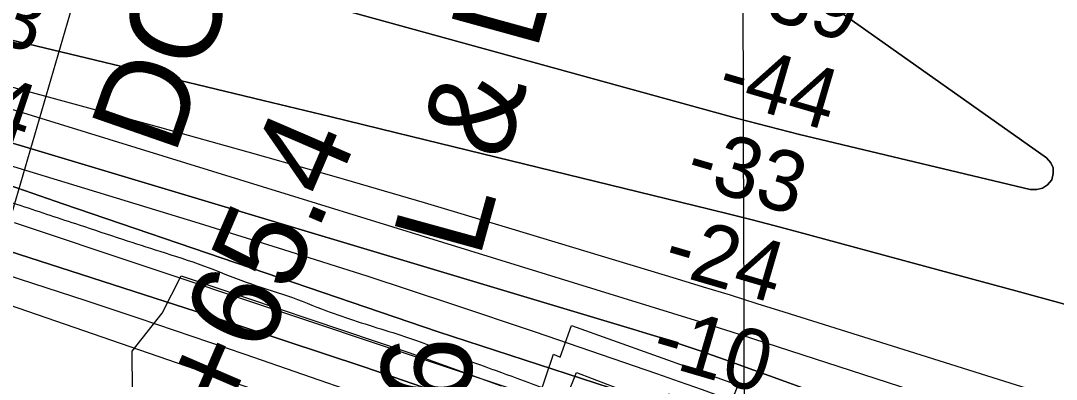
# Model space of a CAD drawing. Extents: x 3361039 to 3398939, y 576572 to 602007.
# Drawn here: x 3390699 to 3391844, y 584956 to 585353 of the extents above; entities that cross this region are included whole.
import ezdxf

# ---------------------------------------------------------------- set-up
doc = ezdxf.new("R2010")
doc.units = 0
for name, color, linetype in [('V-BLDG-OTLN', 7, 'Continuous'), ('V-CHAN-DOCK', 7, 'Continuous'), ('V-CHAN-NAID', 7, 'Continuous'), ('V-GRID-MAJR', 7, 'Continuous'), ('V-RIVR-EDGE', 7, 'Continuous'), ('V-RIVR-RANG', 7, 'Continuous'), ('V-RRAP-RVMT', 7, 'Continuous'), ('V-SITE-VEGE', 7, 'Continuous'), ('V-SURV-IDEN', 7, 'Continuous'), ('V-TOPO-DPTH', 7, 'Continuous'), ('V-TOPO-GNAM-IDEN', 7, 'Continuous'), ('V-TOPO-MINR', 7, 'Continuous'), ('V-TOPO-WATR', 7, 'Continuous')]:
    doc.layers.add(name, color=color, linetype=linetype)

msp = doc.modelspace()

# ---------------------------------------------------------------- linework, layer by layer
at = {"layer": 'V-BLDG-OTLN'}
msp.add_lwpolyline([(3391313.5, 584963.8), (3391365.3, 584943.8), (3391354.9, 584916.8), (3391302.7, 584937)], close=True, dxfattribs=at)
at = {"layer": 'V-CHAN-DOCK'}
msp.add_lwpolyline([(3391216.1, 584431.7), (3391319.4, 584920.6), (3391309.9, 584925.2), (3391300.8, 584899.4), (3391295.2, 584901.5), (3391304, 584926.4), (3391272, 584937.1), (3391287.9, 584984), (3391295.1, 584980.8), (3391307.7, 585015.7), (3391489.2, 584950.8), (3391490.8, 584946.8), (3391478.1, 584915.9), (3391415.4, 584939.9), (3391397.3, 584891.4), (3391323, 584915.4), (3391227.7, 584465.3), (3391220.5, 584430.8), (3391216.1, 584431.7)], dxfattribs=at)
at = {"layer": 'V-GRID-MAJR'}
msp.add_spline([(3391508.2, 582029.8), (3391489.7, 588089), (3391471.2, 594150.1), (3391452.7, 600211.2), (3391452.7, 600213.1)], degree=3, dxfattribs=at)
at = {"layer": 'V-RIVR-EDGE'}
msp.add_spline([(3387368.6, 585771), (3387389, 585767.6), (3387407.3, 585766.1), (3387418.2, 585761.7), (3387425.5, 585756.5), (3387441.6, 585752.8), (3387452.6, 585751.4), (3387462.1, 585753.9), (3387477.4, 585758.2), (3387482.9, 585759.3), (3387491.7, 585759.3), (3387502.3, 585758.2), (3387510.3, 585756.3), (3387521.6, 585753), (3387530.1, 585752.3), (3387538.5, 585752.2), (3387549.8, 585752.2), (3387558.9, 585755.5), (3387571.4, 585756.9), (3387583.4, 585757.3), (3387598.4, 585756.1), (3387629.8, 585749.5), (3387659.8, 585743.5), (3387703.3, 585736.8), (3387727.4, 585734.2), (3387739.1, 585733.5), (3387750.8, 585734.2), (3387753.7, 585731.6), (3387763.2, 585723.9), (3387774.5, 585720.6), (3387790.6, 585719.8), (3387800.1, 585721.6), (3387814, 585720.1), (3387824.6, 585720.1), (3387847.3, 585714.2), (3387884.2, 585709.4), (3387930.2, 585702.7), (3387980.6, 585701.1), (3388035.1, 585696.5), (3388076, 585694.6), (3388096.9, 585693.8), (3388120.3, 585690.5), (3388145.1, 585685.3), (3388171.8, 585682.3), (3388198.8, 585676.8), (3388222.6, 585669.4), (3388245.6, 585660.6), (3388260.9, 585655.4), (3388279.6, 585655.4), (3388291.3, 585658.3), (3388298.9, 585663.7), (3388299.3, 585666.3), (3388299, 585670.7), (3388290.6, 585674.4), (3388291.7, 585677.3), (3388293.9, 585678.4), (3388303, 585677.6), (3388318.7, 585676.5), (3388334.1, 585672.8), (3388354.1, 585663.6), (3388357.1, 585659.9), (3388363.3, 585658.1), (3388368.4, 585658.1), (3388371, 585661), (3388375.3, 585662.1), (3388379, 585661.3), (3388383, 585659.1), (3388383.7, 585654.4), (3388384.1, 585649.3), (3388389.9, 585647.4), (3388406, 585642.3), (3388468.9, 585637.7), (3388491.5, 585635.8), (3388534.6, 585628.4), (3388578.1, 585619.2), (3388610.6, 585613.6), (3388635.9, 585612.1), (3388727.9, 585599.4), (3388768.5, 585591.7), (3388822.6, 585580.9), (3388865, 585570.6), (3388906.6, 585562.8), (3388924.1, 585559.5), (3388938.8, 585562), (3388961.4, 585563.4), (3388974.2, 585560.1), (3389007.5, 585553.4), (3389018.8, 585554.5), (3389027.2, 585555.9), (3389037.1, 585555.9), (3389051.7, 585553.7), (3389061.2, 585553.3), (3389081.3, 585552.1), (3389098.1, 585551), (3389120.4, 585548.7), (3389143.4, 585546.5), (3389160.2, 585542.1), (3389200.8, 585534.7), (3389222.3, 585525.1), (3389247.2, 585519.2), (3389280.4, 585509.6), (3389307.5, 585497.8), (3389334.5, 585487.2), (3389349.5, 585483.1), (3389361.5, 585483.1), (3389382.7, 585479), (3389397, 585476.8), (3389416.7, 585468.7), (3389441.9, 585458.4), (3389464.9, 585451.4), (3389479.5, 585449.2), (3389506.2, 585446.2), (3389533.2, 585447.2), (3389558.5, 585444.2), (3389577.8, 585437.9), (3389603.4, 585431.3), (3389618.7, 585425.1), (3389639.2, 585415.1), (3389657.8, 585410.3), (3389693.2, 585404.8), (3389768.9, 585383), (3389806.5, 585373), (3389854.3, 585362.3), (3389881.7, 585358.6), (3389913.9, 585354.5), (3389953.7, 585349.3), (3390008.2, 585341.8), (3390037.8, 585336.3), (3390074.3, 585327.8), (3390128, 585312.7), (3390164.5, 585301.6), (3390200.7, 585289.8), (3390292.7, 585255.6), (3390327.1, 585241.3), (3390360.7, 585231.7), (3390404.5, 585221), (3390454.9, 585214.3), (3390483.1, 585210.5), (3390491.8, 585209.4), (3390494.4, 585207.2), (3390501.3, 585201), (3390507.9, 585200.6), (3390527.3, 585196.2), (3390545.9, 585195), (3390557.6, 585194.3), (3390574.4, 585189.8), (3390605.5, 585179.5), (3390698.6, 585148.2), (3390763.2, 585126.9), (3390811.1, 585111), (3390852.4, 585097.8), (3390900.9, 585081.6), (3390948.1, 585063.5), (3390993.7, 585048.4), (3391036.8, 585031.9), (3391070.8, 585020.1), (3391140.5, 584997.6), (3391201.5, 584974.1), (3391247.5, 584957.5), (3391310.7, 584933.6), (3391362.2, 584914.8), (3391400.6, 584900.1), (3391441.8, 584885.7), (3391505.4, 584861.1), (3391563.5, 584841.9), (3391658.8, 584807.3), (3391712.8, 584786), (3391758.8, 584767.3), (3391796.1, 584749.6), (3391880.4, 584718.3), (3391926.8, 584701.4), (3391969.2, 584685.2), (3392003.9, 584666.9), (3392040, 584650.3), (3392077.6, 584636), (3392135.7, 584613.2), (3392164.9, 584598.1), (3392196, 584583.8), (3392224.8, 584578.2), (3392263.5, 584567.9), (3392290.6, 584559.8), (3392322.7, 584546.5), (3392396.5, 584512.7), (3392439.9, 584496.2), (3392471.7, 584484.8), (3392502, 584473.3), (3392510.8, 584467.5), (3392535.2, 584458.3), (3392606.1, 584432.9), (3392632.4, 584421.5), (3392666.7, 584406.8), (3392715.6, 584386.9), (3392777.4, 584364.8), (3392827, 584348.3), (3392863.6, 584335.4), (3392897.9, 584321.8), (3392928.6, 584307.8), (3392965.4, 584294.9), (3393010, 584279.1), (3393054.6, 584263.2), (3393092.5, 584248.5), (3393195.2, 584206.6), (3393234.2, 584187.9), (3393264.5, 584173.5), (3393294.1, 584162.1), (3393336.8, 584147.4), (3393374.5, 584136.3), (3393402.2, 584127.5), (3393414.3, 584119.8), (3393435.4, 584109.1), (3393459.2, 584098.1), (3393478.9, 584087.5), (3393513.6, 584076.4), (3393541.7, 584067.2), (3393588.1, 584047.4), (3393643.2, 584028.9), (3393668.4, 584018.3), (3393699.8, 584005), (3393737.1, 583991.8), (3393781.7, 583976), (3393884.7, 583943.2), (3393927, 583928.8), (3393981.1, 583908.2), (3394043.9, 583885.4), (3394095.8, 583868.1), (3394154.9, 583847.1), (3394200.2, 583830.5), (3394247, 583816.2), (3394293, 583801.4), (3394349.6, 583781.2), (3394409.1, 583754.7), (3394451.8, 583730.5), (3394470.5, 583720.2), (3394481.8, 583715.4), (3394494.2, 583713.6), (3394502.6, 583708.1), (3394507.3, 583700.4), (3394511.3, 583697.8), (3394522.7, 583692.3), (3394557.3, 583675.8), (3394600.4, 583659.9), (3394658.1, 583638.9), (3394704.5, 583623.5), (3394760.4, 583607.6), (3394824, 583588.8), (3394867.8, 583570.8), (3394925.9, 583546.9), (3394972.2, 583528.9), (3394995.6, 583520), (3395064.7, 583504.2), (3395088.4, 583499.3), (3395120.2, 583491.6), (3395149.1, 583480.5), (3395173.2, 583476.8), (3395201.3, 583471.3), (3395236.4, 583459.9), (3395256.8, 583451.8), (3395280.9, 583445.5), (3395300.3, 583445.1), (3395316.7, 583440.7), (3395324.4, 583433.3), (3395335.3, 583426), (3395353.6, 583417.9), (3395398.9, 583403.9), (3395426.3, 583397.2), (3395442, 583391), (3395455.9, 583383.3), (3395476, 583377.8), (3395495.7, 583369.3), (3395511, 583368.2), (3395530.4, 583365.9), (3395550.5, 583361.8), (3395654.6, 583334.9), (3395704.7, 583322.4), (3395743.7, 583306.9), (3395765.3, 583295.5), (3395788.3, 583286.3), (3395816.4, 583278.9), (3395861.7, 583270.8), (3395916.2, 583261.5), (3395960.7, 583252.6), (3396008.6, 583242.6), (3396060.8, 583230.5), (3396093.4, 583222.3), (3396135.4, 583208.7), (3396170.1, 583199.8), (3396204.4, 583191.3), (3396254.8, 583177.3), (3396301.2, 583165.9), (3396364.4, 583152.9), (3396399.1, 583144.4), (3396426.9, 583138.5), (3396463.1, 583133), (3396489.8, 583132.9), (3396523.4, 583130.2), (3396607.8, 583114), (3396670.3, 583102.1), (3396708.3, 583095.4), (3396743, 583089.5), (3396775.1, 583083.9)], degree=3, dxfattribs=at)
at = {"layer": 'V-RRAP-RVMT'}
msp.add_lwpolyline([(3390685.7, 585129), (3390783.7, 585465.6), (3390648.8, 585504.8), (3390652.2, 585515.7), (3390497.3, 585563.3), (3390495.9, 585558.8), (3390372.4, 585595.5), (3390373.7, 585599.7), (3390218.6, 585646.7), (3390217.1, 585641.8), (3390080.1, 585682.4), (3390078.7, 585677.7), (3389945.1, 585716.3), (3389952.9, 585741.6), (3389804, 585787.6), (3389799.7, 585774.2), (3389655.5, 585815.8), (3389654.5, 585812.6)], dxfattribs=at)
at = {"layer": 'V-SITE-VEGE'}
msp.add_lwpolyline([(3390822.2, 584942.7), (3390821.7, 584987.3), (3390855, 585029.4), (3390875.9, 585070.5), (3391128, 584985.7), (3391230.1, 584948.8)], dxfattribs=at)
at = {"layer": 'V-TOPO-DPTH'}
for points in [[(3391605.6, 585361.8), (3391833.3, 585200.8), (3391837.9, 585195.5), (3391840.7, 585189.8), (3391840.7, 585183.5), (3391839, 585176.7), (3391834.3, 585171.2), (3391829, 585167.3), (3391822.5, 585165.8), (3391815.2, 585166), (3391583.2, 585221.1), (3391560.2, 585226.7), (3391537.2, 585232.5), (3391514.3, 585238.5), (3391491.5, 585244.6), (3390782.9, 585439.8)], [(3390782.9, 585439.8), (3391491.5, 585244.6), (3391514.3, 585238.5), (3391537.2, 585232.5), (3391560.2, 585226.7), (3391583.2, 585221.1), (3391815.2, 585166), (3391822.5, 585165.8), (3391829, 585167.3), (3391834.3, 585171.2), (3391839, 585176.7), (3391840.7, 585183.5), (3391840.7, 585189.8), (3391837.9, 585195.5), (3391833.3, 585200.8), (3391605.6, 585361.8)], [(3391896.5, 585027.4), (3391799.4, 585053.9), (3391702.2, 585080.3), (3391555.3, 585120), (3391531.6, 585126.3), (3391507.8, 585132.5), (3391483.9, 585138.5), (3391460.1, 585144.4), (3391114.1, 585228.6), (3391040.5, 585246.5), (3390966.9, 585264.3), (3390893.3, 585282.1), (3390819.7, 585299.8), (3390742.8, 585318.2), (3390707.6, 585326.6), (3390672.4, 585334.9)], [(3390672.4, 585334.9), (3390707.6, 585326.6), (3390742.8, 585318.2), (3390819.7, 585299.8), (3390893.3, 585282.1), (3390966.9, 585264.3), (3391040.5, 585246.5), (3391114.1, 585228.6), (3391460.1, 585144.4), (3391483.9, 585138.5), (3391507.8, 585132.5), (3391531.6, 585126.3), (3391555.3, 585120), (3391702.2, 585080.3), (3391799.4, 585053.9), (3391896.5, 585027.4)], [(3390678.7, 585282.1), (3390852.2, 585234.7), (3390949.9, 585207.6), (3391047.4, 585179.9), (3391144.7, 585151.5), (3391241.8, 585122.5), (3391423.6, 585067.6), (3391453.4, 585058.5), (3391483.2, 585049.4), (3391513, 585040.1), (3391542.7, 585030.8), (3391694.3, 584983.1), (3391799.9, 584950), (3391905.5, 584917.2), (3392011.2, 584884.7), (3392117, 584852.4), (3392327.2, 584788.6), (3392352.5, 584780.9), (3392377.9, 584773.2), (3392403.2, 584765.6), (3392428.6, 584758.1), (3392783.6, 584652.3), (3392834.9, 584637), (3392886.4, 584621.7)], [(3390678.7, 585282.1), (3390852.2, 585234.7), (3390949.9, 585207.6), (3391047.4, 585179.9), (3391144.7, 585151.5), (3391241.8, 585122.5), (3391423.6, 585067.6), (3391453.4, 585058.5), (3391483.2, 585049.4), (3391513, 585040.1), (3391542.7, 585030.8), (3391694.3, 584983.1), (3391799.9, 584950), (3391905.5, 584917.2), (3392011.2, 584884.7), (3392117, 584852.4), (3392327.2, 584788.6), (3392352.5, 584780.9), (3392377.9, 584773.2), (3392403.2, 584765.6), (3392428.6, 584758.1), (3392783.6, 584652.3), (3392834.9, 584637), (3392886.4, 584621.7)], [(3393031.5, 584404.1), (3392383, 584655.6), (3392365.1, 584662), (3392347.2, 584668.5), (3392329.2, 584674.9), (3392311.3, 584681.3), (3391705.7, 584895.7), (3391665.3, 584910.1), (3391624.9, 584924.5), (3391584.6, 584939.1), (3391544.3, 584953.7), (3391492.3, 584972.7), (3391478, 584977.8), (3391463.6, 584982.9), (3391449.2, 584987.9), (3391434.8, 584992.8), (3391420.3, 584997.6), (3391405.8, 585002.3), (3391391.2, 585006.9), (3391376.6, 585011.3), (3390699.4, 585214.1), (3390668.7, 585223.2)], [(3390668.7, 585223.2), (3390699.4, 585214.1), (3391376.6, 585011.3), (3391391.2, 585006.9), (3391405.8, 585002.3), (3391420.3, 584997.6), (3391434.8, 584992.8), (3391449.2, 584987.9), (3391463.6, 584982.9), (3391478, 584977.8), (3391492.3, 584972.7), (3391544.3, 584953.7), (3391584.6, 584939.1), (3391624.9, 584924.5), (3391665.3, 584910.1), (3391705.7, 584895.7), (3392311.3, 584681.3), (3392329.2, 584674.9), (3392347.2, 584668.5), (3392365.1, 584662), (3392383, 584655.6), (3393031.5, 584404.1)], [(3392928.6, 584331.6), (3392676, 584440.3), (3392339.2, 584576.6), (3392323.1, 584583.4), (3392305.2, 584590.3), (3391596.6, 584849.1), (3391504.7, 584888.5), (3391448.6, 584913.4), (3391429.9, 584921.1), (3391160.2, 585008.6), (3390745.1, 585150.1), (3390651.5, 585182.7)], [(3390651.5, 585182.7), (3390745.1, 585150.1), (3391160.2, 585008.6), (3391429.9, 584921.1), (3391448.6, 584913.4), (3391504.7, 584888.5), (3391596.6, 584849.1), (3392305.2, 584590.3), (3392323.1, 584583.4), (3392339.2, 584576.6), (3392676, 584440.3), (3392928.6, 584331.6)], [(3392986.7, 584240.6), (3392333.6, 584495.2), (3392300.5, 584509), (3392267.3, 584522.7), (3392234.1, 584536.4), (3392180.2, 584558.7), (3392119.9, 584583.3), (3392059.6, 584607.5), (3391998.9, 584631.1), (3391938.2, 584654.4), (3391473.7, 584830.1), (3391448.8, 584839.4), (3391423.9, 584848.6), (3391399, 584857.6), (3391374, 584866.5), (3391251.3, 584909.9), (3391164.7, 584940.1), (3391078.1, 584969.8), (3390991.1, 584998.8), (3390904, 585027.3), (3390649.8, 585109.3)]]:
    msp.add_lwpolyline(points, dxfattribs=at)
at = {"layer": 'V-TOPO-MINR'}
for points in [[(3391605.6, 585361.8), (3391833.3, 585200.8), (3391837.9, 585195.5), (3391840.7, 585189.8), (3391840.7, 585183.5), (3391839, 585176.7), (3391834.3, 585171.2), (3391829, 585167.3), (3391822.5, 585165.8), (3391815.2, 585166), (3391583.2, 585221.1), (3391560.2, 585226.7), (3391537.2, 585232.5), (3391514.3, 585238.5), (3391491.5, 585244.6), (3390782.9, 585439.8)], [(3390672.4, 585334.9), (3390707.6, 585326.6), (3390742.8, 585318.2), (3390819.7, 585299.8), (3390893.3, 585282.1), (3390966.9, 585264.3), (3391040.5, 585246.5), (3391114.1, 585228.6), (3391460.1, 585144.4), (3391483.9, 585138.5), (3391507.8, 585132.5), (3391531.6, 585126.3), (3391555.3, 585120), (3391702.2, 585080.3), (3391799.4, 585053.9), (3391896.5, 585027.4)], [(3390678.7, 585282.1), (3390852.2, 585234.7), (3390949.9, 585207.6), (3391047.4, 585179.9), (3391144.7, 585151.5), (3391241.8, 585122.5), (3391423.6, 585067.6), (3391453.4, 585058.5), (3391483.2, 585049.4), (3391513, 585040.1), (3391542.7, 585030.8), (3391694.3, 584983.1), (3391799.9, 584950), (3391905.5, 584917.2), (3392011.2, 584884.7), (3392117, 584852.4), (3392327.2, 584788.6), (3392352.5, 584780.9), (3392377.9, 584773.2), (3392403.2, 584765.6), (3392428.6, 584758.1), (3392783.6, 584652.3), (3392834.9, 584637), (3392886.4, 584621.7)], [(3390656, 585264.9), (3391449.4, 585020), (3391460.9, 585016.4), (3391472.4, 585012.8), (3391483.9, 585009.1), (3391495.4, 585005.4), (3392170, 584786.8), (3392202.3, 584776.3), (3392234.5, 584765.7), (3392266.6, 584755.1), (3392298.8, 584744.3), (3392358, 584724.5), (3392360.5, 584723.7), (3392363.1, 584722.8), (3392365.6, 584722), (3392368.2, 584721.1), (3392655.4, 584625), (3392725.2, 584601.8), (3392795, 584578.6), (3392864.8, 584555.5)], [(3390668.7, 585223.2), (3390699.4, 585214.1), (3391376.6, 585011.3), (3391391.2, 585006.9), (3391405.8, 585002.3), (3391420.3, 584997.6), (3391434.8, 584992.8), (3391449.2, 584987.9), (3391463.6, 584982.9), (3391478, 584977.8), (3391492.3, 584972.7), (3391544.3, 584953.7), (3391584.6, 584939.1), (3391624.9, 584924.5), (3391665.3, 584910.1), (3391705.7, 584895.7), (3392311.3, 584681.3), (3392329.2, 584674.9), (3392347.2, 584668.5), (3392365.1, 584662), (3392383, 584655.6), (3393031.5, 584404.1)], [(3390668.5, 585198), (3390896, 585128.7), (3390989.3, 585099.8), (3391082.4, 585070.2), (3391175.2, 585039.7), (3391267.7, 585008.5), (3391401.9, 584962.5), (3391427.1, 584953.7), (3391452.4, 584944.9), (3391477.5, 584935.8), (3391502.7, 584926.6), (3392077.3, 584714.2), (3392119.9, 584698.4), (3392162.5, 584682.6), (3392205.1, 584666.7), (3392247.6, 584650.9), (3392251.7, 584649.3), (3392292.2, 584634.1), (3392332.6, 584618.9), (3392373, 584603.5), (3392413.4, 584588.1), (3393024.8, 584355.3)], [(3390691.3, 585129.6), (3391270.7, 584936.1), (3391297.9, 584927), (3391325, 584917.7), (3391352.1, 584908.2), (3391379.1, 584898.7), (3391406.1, 584889), (3391433, 584879.2), (3391459.9, 584869.3), (3391486.8, 584859.4), (3391649.5, 584798.6), (3391757.7, 584758.2), (3391865.9, 584717.8)], [(3390649.8, 585109.3), (3390904, 585027.3), (3390991.1, 584998.8), (3391078.1, 584969.8), (3391164.7, 584940.1), (3391251.3, 584909.9), (3391374, 584866.5), (3391399, 584857.6), (3391423.9, 584848.6), (3391448.8, 584839.4), (3391473.7, 584830.1), (3391938.2, 584654.4), (3391998.9, 584631.1), (3392059.6, 584607.5), (3392119.9, 584583.3), (3392180.2, 584558.7), (3392234.1, 584536.4), (3392267.3, 584522.7), (3392300.5, 584509), (3392333.6, 584495.2), (3392986.7, 584240.6)], [(3390617.2, 585092.9), (3390711.5, 585062.5), (3390770.4, 585043.3), (3390829.2, 585023.9), (3390887.9, 585004), (3390946.5, 584983.9), (3391393, 584829), (3391404.4, 584825), (3391415.8, 584821), (3391427.2, 584816.8), (3391438.5, 584812.5), (3391558.5, 584767), (3391629.6, 584739.5), (3391700.5, 584711.4), (3391771, 584682.4), (3391841.3, 584652.9), (3392226.2, 584488.1), (3392256.5, 584475.3), (3393034.3, 584188.9)], [(3390612.8, 585063.4), (3391305.1, 584824.7), (3391322, 584818.7), (3391338.9, 584812.3), (3391355.5, 584805.7), (3391372.1, 584798.7), (3391388.5, 584791.4), (3391404.9, 584784), (3391421.1, 584776.3), (3392242.1, 584407), (3392267.6, 584396.7), (3392293, 584386.4), (3392910, 584097.1)]]:
    msp.add_lwpolyline(points, dxfattribs=at)
at = {"layer": 'V-TOPO-WATR'}
msp.add_lwpolyline([(3392928.6, 584331.6), (3392676, 584440.3), (3392339.2, 584576.6), (3392323.1, 584583.4), (3392305.2, 584590.3), (3391596.6, 584849.1), (3391504.7, 584888.5), (3391448.6, 584913.4), (3391429.9, 584921.1), (3391160.2, 585008.6), (3390745.1, 585150.1), (3390651.5, 585182.7)], dxfattribs=at)

# ---------------------------------------------------------------- texts
at = {"layer": 'V-CHAN-NAID'}
msp.add_text('L & L FLEETING, MILE 175 (176.0) (2)', height=100, rotation=74.6237, dxfattribs=at).set_placement((3391205.9, 585088.5))
at = {"layer": 'V-RIVR-RANG'}
for s, rotation, p in [('-39', 343.702, (3391490.9, 585364.2)), ('-33', 341.5598, (3390589.8, 585356.5)), ('-44', 343.702, (3391466.2, 585267.2)), ('-14', 341.5598, (3390577.8, 585255.1)), ('-33', 343.702, (3391431.1, 585173.3)), ('-24', 343.702, (3391406.6, 585076.3)), ('-10', 343.702, (3391393.4, 584976))]:
    msp.add_text(s, height=67, rotation=rotation, dxfattribs=at).set_placement(p)
at = {"layer": 'V-SURV-IDEN'}
for s, rotation, p in [('16+65.4', 66.7217, (3390878.1, 584773.2)), ('21+96.6', 88.1807, (3391183.2, 584514.8))]:
    msp.add_text(s, height=100, rotation=rotation, dxfattribs=at).set_placement(p)
at = {"layer": 'V-TOPO-GNAM-IDEN'}
msp.add_text('DONALDSONVILLE LDG.', height=100, rotation=70.8012, dxfattribs=at).set_placement((3390868.7, 585202.3))

doc.saveas('drawing.dxf')
